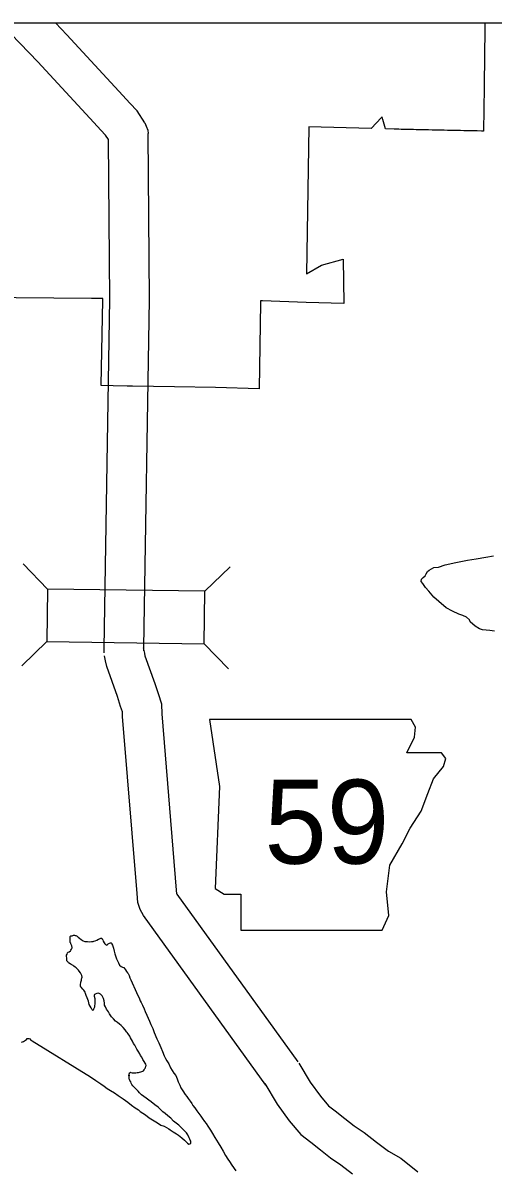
# Model space of a CAD drawing. Extents: x 1370567 to 1373900, y 377514 to 379648.
# Drawn here: x 1370913.9 to 1370949.4, y 379466.1 to 379552.5 of the extents above; entities that cross this region are included whole.
import ezdxf

# ---------------------------------------------------------------- set-up
doc = ezdxf.new("R2010")
doc.units = 0
doc.layers.add('Default', color=7, linetype='Continuous')
doc.layers.add('Survey Symbols', color=7, linetype='Continuous')

msp = doc.modelspace()

# ---------------------------------------------------------------- linework, layer by layer
at = {"layer": 'Default'}
for p, q in [((1370915.775, 379509.822), (1370913.934, 379511.715)), ((1370927.654, 379509.657), (1370929.546, 379511.498)), ((1370915.72, 379505.863), (1370913.827, 379504.022)), ((1370927.599, 379505.698), (1370929.439, 379503.805))]:
    msp.add_line(p, q, dxfattribs=at)
for points in [[(1370920.362, 379543.744), (1370920.151, 379544.066), (1370919.798, 379544.447), (1370919.256, 379545.024), (1370915.03, 379549.598), (1370913.026, 379551.692), (1370912.226, 379552.541)], [(1370923.119, 379545.008), (1370922.524, 379545.918), (1370921.992, 379546.493), (1370921.45, 379547.07), (1370917.216, 379551.653), (1370916.365, 379552.541)], [(1370948.789, 379552.541), (1370948.771, 379551.179), (1370948.767, 379550.923), (1370948.747, 379549.429), (1370948.746, 379549.328), (1370948.735, 379548.543), (1370948.728, 379548.044), (1370948.723, 379547.68), (1370948.701, 379546.03), (1370948.678, 379544.379), (1370948.529, 379544.382), (1370948.204, 379544.388), (1370947.954, 379544.393), (1370947.704, 379544.398), (1370947.454, 379544.403), (1370947.204, 379544.408), (1370946.954, 379544.413), (1370946.704, 379544.418), (1370946.454, 379544.423), (1370946.203, 379544.428), (1370945.953, 379544.433), (1370945.703, 379544.437), (1370945.453, 379544.442), (1370945.113, 379544.449), (1370944.807, 379544.456), (1370944.529, 379544.463), (1370944.513, 379544.463), (1370944.279, 379544.468), (1370944.24, 379544.469), (1370944.1, 379544.473), (1370944.054, 379544.474), (1370943.96, 379544.476), (1370943.823, 379544.479), (1370943.67, 379544.483), (1370943.596, 379544.484), (1370943.386, 379544.489), (1370943.369, 379544.489), (1370943.142, 379544.495), (1370943.111, 379544.495), (1370942.916, 379544.5), (1370942.839, 379544.502), (1370942.689, 379544.505), (1370942.564, 379544.508), (1370942.466, 379544.51), (1370942.285, 379544.515), (1370942.232, 379544.516), (1370941.987, 379544.521), (1370941.935, 379544.523), (1370941.289, 379544.538), (1370941.08, 379545.241), (1370941.02, 379545.444), (1370940.989, 379545.41), (1370940.205, 379544.563), (1370935.483, 379544.696), (1370935.33, 379533.601), (1370936.451, 379534.268), (1370938.091, 379534.722), (1370938.138, 379531.373), (1370935.3, 379531.432), (1370931.999, 379531.561), (1370931.848, 379531.567), (1370931.846, 379531.417), (1370931.751, 379524.935)], [(1370923.119, 379545.008), (1370923.217, 379544.758), (1370923.333, 379544.455), (1370923.364, 379544.199)], [(1370920.052, 379505.011), (1370920.034, 379505.357), (1370920.466, 379531.696), (1370920.367, 379543.747)], [(1370923.048, 379505.167), (1370923.035, 379505.41), (1370923.466, 379531.683), (1370923.364, 379544.199)], [(1370931.751, 379524.935), (1370928.449, 379525.024), (1370925.351, 379525.077), (1370922.177, 379525.131), (1370921.777, 379525.138), (1370920.733, 379525.156), (1370919.825, 379525.171), (1370919.825, 379525.186), (1370919.825, 379525.196), (1370919.932, 379531.621), (1370919.934, 379531.744), (1370919.306, 379531.75), (1370919.295, 379531.75), (1370919.098, 379531.752), (1370913.4, 379531.805), (1370908.872, 379531.864)], [(1370949.513, 379506.638), (1370949.154, 379506.686), (1370948.605, 379506.752), (1370948.385, 379506.831), (1370948.044, 379507.029), (1370947.673, 379507.347), (1370947.622, 379507.487), (1370947.392, 379507.696), (1370947.131, 379507.824), (1370946.812, 379507.922), (1370946.331, 379508.159), (1370945.851, 379508.396), (1370945.299, 379508.873), (1370944.938, 379509.221), (1370944.566, 379509.65), (1370944.304, 379509.938), (1370944.103, 379510.237), (1370943.982, 379510.387), (1370944.001, 379510.567), (1370944.12, 379510.698), (1370944.278, 379510.829), (1370944.357, 379510.97), (1370944.446, 379511.141), (1370944.575, 379511.242), (1370944.754, 379511.353), (1370944.923, 379511.454), (1370945.291, 379511.477), (1370945.789, 379511.66), (1370946.586, 379511.815), (1370947.462, 379512.011), (1370948.13, 379512.106), (1370948.847, 379512.221), (1370949.435, 379512.335)], [(1370934.677, 379474.148), (1370925.56, 379486.798), (1370925.541, 379486.832), (1370925.517, 379487.112), (1370924.431, 379500.414), (1370924.387, 379501.132), (1370924.134, 379501.903), (1370923.884, 379502.669), (1370923.144, 379504.755), (1370923.102, 379504.979), (1370923.021, 379505.383)], [(1370932.244, 379472.394), (1370923.016, 379485.196), (1370922.773, 379485.643), (1370922.588, 379486.166), (1370922.528, 379486.861), (1370921.439, 379500.199), (1370921.416, 379500.562), (1370921.283, 379500.97), (1370921.044, 379501.702), (1370920.238, 379503.971), (1370920.156, 379504.408), (1370920.079, 379504.795)], [(1370918.306, 379480.752), (1370918.256, 379480.862), (1370918.166, 379480.992), (1370918.106, 379481.052), (1370918.036, 379481.132), (1370917.925, 379481.251), (1370917.865, 379481.301), (1370917.765, 379481.361), (1370917.705, 379481.411), (1370917.555, 379481.48), (1370917.485, 379481.54), (1370917.355, 379481.63), (1370917.335, 379481.67), (1370917.235, 379481.769), (1370917.215, 379481.899), (1370917.224, 379481.99), (1370917.204, 379482.1), (1370917.213, 379482.2), (1370917.243, 379482.27), (1370917.283, 379482.37), (1370917.332, 379482.411), (1370917.392, 379482.451), (1370917.492, 379482.531), (1370917.531, 379482.581), (1370917.571, 379482.652), (1370917.621, 379482.742), (1370917.62, 379482.802), (1370917.61, 379482.862), (1370917.6, 379482.902), (1370917.59, 379482.952), (1370917.54, 379483.042), (1370917.519, 379483.102), (1370917.479, 379483.162), (1370917.469, 379483.262), (1370917.479, 379483.362), (1370917.468, 379483.442), (1370917.478, 379483.512), (1370917.478, 379483.562), (1370917.488, 379483.612), (1370917.537, 379483.643), (1370917.627, 379483.663), (1370917.737, 379483.694), (1370917.807, 379483.694), (1370917.866, 379483.684), (1370917.916, 379483.674), (1370917.956, 379483.654), (1370917.996, 379483.624), (1370918.076, 379483.555), (1370918.177, 379483.475), (1370918.307, 379483.385), (1370918.387, 379483.326), (1370918.447, 379483.276), (1370918.577, 379483.226), (1370918.686, 379483.216), (1370918.786, 379483.217), (1370918.966, 379483.208), (1370919.085, 379483.218), (1370919.205, 379483.238), (1370919.255, 379483.249), (1370919.355, 379483.289), (1370919.484, 379483.33), (1370919.624, 379483.4), (1370919.693, 379483.43), (1370919.793, 379483.491), (1370919.833, 379483.491), (1370919.883, 379483.441), (1370919.903, 379483.411), (1370919.933, 379483.341), (1370919.973, 379483.241), (1370920.034, 379483.131), (1370920.104, 379483.042), (1370920.144, 379482.992), (1370920.184, 379482.972), (1370920.224, 379482.962), (1370920.284, 379482.992), (1370920.343, 379483.042), (1370920.393, 379483.083), (1370920.453, 379483.113), (1370920.513, 379483.123), (1370920.563, 379483.123), (1370920.603, 379483.093), (1370920.623, 379483.074), (1370920.633, 379483.024), (1370920.663, 379482.944), (1370920.744, 379482.734), (1370920.804, 379482.504), (1370920.855, 379482.304), (1370920.926, 379482.073), (1370920.986, 379481.914), (1370921.046, 379481.764), (1370921.127, 379481.614), (1370921.207, 379481.454), (1370921.327, 379481.334), (1370921.427, 379481.294), (1370921.517, 379481.265), (1370921.587, 379481.195), (1370921.648, 379481.095), (1370921.738, 379480.975), (1370921.798, 379480.875), (1370921.848, 379480.815), (1370921.919, 379480.666)], [(1370921.922, 379473.007), (1370921.917, 379473.117), (1370921.926, 379473.197), (1370921.936, 379473.237), (1370921.956, 379473.277), (1370921.966, 379473.307), (1370921.986, 379473.327), (1370921.996, 379473.347), (1370922.026, 379473.357), (1370922.065, 379473.347), (1370922.165, 379473.328), (1370922.285, 379473.328), (1370922.425, 379473.329), (1370922.544, 379473.339), (1370922.624, 379473.35), (1370922.704, 379473.37), (1370922.804, 379473.39), (1370922.883, 379473.411), (1370922.953, 379473.431), (1370923.023, 379473.471), (1370923.073, 379473.541), (1370923.122, 379473.642), (1370923.152, 379473.702), (1370923.191, 379473.822), (1370923.211, 379473.872), (1370923.201, 379473.962), (1370923.14, 379474.052), (1370923.07, 379474.182), (1370922.97, 379474.332), (1370922.879, 379474.512), (1370922.789, 379474.632), (1370922.729, 379474.742), (1370922.618, 379474.951), (1370922.518, 379475.111), (1370922.428, 379475.261), (1370922.347, 379475.401), (1370922.267, 379475.541), (1370922.186, 379475.701), (1370922.116, 379475.841), (1370922.036, 379475.97), (1370921.975, 379476.09), (1370921.855, 379476.26), (1370921.775, 379476.36), (1370921.725, 379476.42), (1370921.624, 379476.57), (1370921.484, 379476.739), (1370921.334, 379476.889), (1370921.204, 379476.999), (1370921.054, 379477.118), (1370920.904, 379477.228), (1370920.753, 379477.397), (1370920.603, 379477.547), (1370920.453, 379477.767), (1370920.362, 379477.917), (1370920.232, 379478.116), (1370920.141, 379478.296), (1370920.081, 379478.426), (1370920.061, 379478.576), (1370920.04, 379478.746), (1370919.989, 379478.936), (1370919.889, 379479.136), (1370919.779, 379479.266), (1370919.679, 379479.306), (1370919.589, 379479.325), (1370919.499, 379479.295), (1370919.409, 379479.275), (1370919.38, 379479.264), (1370919.32, 379479.224), (1370919.29, 379479.174), (1370919.28, 379479.114), (1370919.331, 379478.924), (1370919.342, 379478.744), (1370919.332, 379478.503), (1370919.323, 379478.393), (1370919.303, 379478.273), (1370919.274, 379478.173), (1370919.244, 379478.113), (1370919.214, 379478.052), (1370919.185, 379478.022), (1370919.144, 379478.072), (1370919.064, 379478.232), (1370918.923, 379478.482), (1370918.853, 379478.722), (1370918.772, 379478.972), (1370918.691, 379479.162), (1370918.641, 379479.292), (1370918.601, 379479.402), (1370918.5, 379479.562), (1370918.43, 379479.621), (1370918.3, 379479.771), (1370918.26, 379479.821), (1370918.26, 379479.881), (1370918.269, 379479.961), (1370918.289, 379480.151), (1370918.308, 379480.222), (1370918.328, 379480.322), (1370918.338, 379480.402), (1370918.357, 379480.462), (1370918.377, 379480.542), (1370918.347, 379480.652), (1370918.306, 379480.752)], [(1370921.919, 379480.666), (1370921.989, 379480.486), (1370922.06, 379480.326), (1370922.482, 379479.376), (1370922.703, 379478.906), (1370922.764, 379478.746), (1370922.834, 379478.617), (1370922.935, 379478.417), (1370923.055, 379478.157), (1370923.146, 379477.947), (1370923.267, 379477.667), (1370923.357, 379477.447), (1370923.468, 379477.217), (1370923.569, 379476.957), (1370923.709, 379476.657), (1370923.83, 379476.368), (1370924.032, 379475.878), (1370924.182, 379475.578), (1370924.313, 379475.238), (1370924.444, 379474.918), (1370924.585, 379474.608), (1370924.686, 379474.398), (1370924.786, 379474.229), (1370924.917, 379474.009), (1370925.057, 379473.699), (1370925.188, 379473.489), (1370925.298, 379473.289), (1370925.467, 379473.123)], [(1370913.796, 379475.639), (1370913.945, 379475.68), (1370914.035, 379475.74), (1370914.104, 379475.781), (1370914.174, 379475.831), (1370914.244, 379475.901), (1370914.303, 379475.912), (1370914.363, 379475.902), (1370914.423, 379475.872), (1370914.513, 379475.792), (1370914.603, 379475.722), (1370919.015, 379473.027)], [(1370934.747, 379474.041), (1370935.606, 379472.607), (1370936.374, 379471.549), (1370936.97, 379470.84), (1370937.48, 379470.45), (1370938.219, 379469.87), (1370938.92, 379469.321), (1370939.664, 379468.803), (1370940.604, 379468.09), (1370941.497, 379467.409), (1370942.445, 379466.877), (1370943.728, 379465.851)], [(1370919.015, 379473.027), (1370919.417, 379472.751), (1370919.79, 379472.494), (1370920.041, 379472.307), (1370920.273, 379472.129), (1370920.534, 379471.972), (1370920.816, 379471.804), (1370921.107, 379471.617), (1370921.48, 379471.351), (1370921.832, 379471.094), (1370922.104, 379470.887), (1370922.396, 379470.68), (1370922.627, 379470.522), (1370922.758, 379470.393), (1370922.969, 379470.275), (1370923.161, 379470.137), (1370923.453, 379469.93), (1370923.684, 379469.772), (1370924.066, 379469.546), (1370924.327, 379469.378), (1370924.568, 379469.281), (1370924.93, 379469.084), (1370925.02, 379469.025), (1370925.262, 379468.877), (1370925.493, 379468.719), (1370925.664, 379468.611), (1370925.896, 379468.423), (1370926.118, 379468.225), (1370926.269, 379468.077), (1370926.339, 379468.018), (1370926.44, 379467.938), (1370926.52, 379467.949), (1370926.579, 379467.99), (1370926.599, 379468.04), (1370926.598, 379468.09), (1370926.588, 379468.17), (1370926.547, 379468.24), (1370926.516, 379468.3), (1370926.486, 379468.369), (1370926.465, 379468.409), (1370926.353, 379468.648), (1370926.252, 379468.787), (1370926.11, 379468.946), (1370925.918, 379469.134), (1370925.676, 379469.372), (1370925.475, 379469.52), (1370925.283, 379469.678), (1370925.081, 379469.886), (1370924.86, 379470.074), (1370924.648, 379470.242), (1370924.477, 379470.381), (1370924.285, 379470.549), (1370924.124, 379470.717), (1370923.872, 379470.915), (1370923.6, 379471.122), (1370923.419, 379471.26), (1370923.217, 379471.399), (1370923.036, 379471.527), (1370922.865, 379471.645), (1370922.724, 379471.814), (1370922.602, 379471.943), (1370922.471, 379472.092), (1370922.34, 379472.22), (1370922.219, 379472.349), (1370922.138, 379472.448), (1370922.087, 379472.548), (1370922.046, 379472.638), (1370921.985, 379472.747), (1370921.964, 379472.807), (1370921.943, 379472.867), (1370921.933, 379472.927), (1370921.922, 379473.007), (1370921.951, 379473.137)], [(1370925.467, 379473.123), (1370925.56, 379472.874), (1370925.632, 379472.644), (1370925.745, 379472.375), (1370925.827, 379472.186), (1370925.989, 379471.947), (1370926.151, 379471.689), (1370926.273, 379471.53), (1370926.394, 379471.371), (1370926.526, 379471.172), (1370926.658, 379471.003), (1370926.749, 379470.854), (1370926.891, 379470.675), (1370927.043, 379470.457), (1370927.195, 379470.258), (1370927.266, 379470.159), (1370927.347, 379470.05), (1370927.449, 379469.89), (1370927.631, 379469.642), (1370927.733, 379469.503), (1370927.864, 379469.304), (1370927.976, 379469.135), (1370928.068, 379468.986), (1370928.21, 379468.747), (1370928.393, 379468.449), (1370928.647, 379468.031), (1370928.84, 379467.713), (1370929.033, 379467.404), (1370929.216, 379467.076), (1370929.389, 379466.808), (1370929.511, 379466.619), (1370929.683, 379466.34), (1370929.978, 379465.913)], [(1370932.173, 379472.501), (1370933.1, 379470.952), (1370934.009, 379469.7), (1370934.885, 379468.659), (1370935.642, 379468.079), (1370936.369, 379467.508), (1370937.136, 379466.907), (1370937.899, 379466.376), (1370938.788, 379465.702)], [(1370926.864, 379470.71), (1370926.891, 379470.675), (1370927.043, 379470.457), (1370927.195, 379470.258), (1370927.266, 379470.159), (1370927.347, 379470.05), (1370927.449, 379469.89), (1370927.631, 379469.642), (1370927.733, 379469.503), (1370927.864, 379469.304), (1370927.976, 379469.135), (1370928.068, 379468.986), (1370928.21, 379468.747), (1370928.393, 379468.449), (1370928.647, 379468.031), (1370928.84, 379467.713), (1370929.033, 379467.404), (1370929.216, 379467.076), (1370929.389, 379466.808), (1370929.511, 379466.619), (1370929.683, 379466.34), (1370929.978, 379465.913)]]:
    msp.add_lwpolyline(points, dxfattribs=at)
for points in [[(1370915.72, 379505.863), (1370927.599, 379505.698), (1370927.654, 379509.657), (1370915.775, 379509.822)], [(1370927.994, 379499.99), (1370928.756, 379494.914), (1370928.417, 379487.217), (1370929.094, 379486.794), (1370930.363, 379486.794), (1370930.363, 379484.087), (1370941.021, 379484.087), (1370941.529, 379485.187), (1370941.359, 379486.963), (1370941.613, 379488.993), (1370942.544, 379490.6), (1370943.136, 379491.785), (1370943.982, 379493.053), (1370944.489, 379494.407), (1370944.912, 379495.507), (1370945.673, 379496.437), (1370945.843, 379497.029), (1370945.504, 379497.452), (1370942.882, 379497.452), (1370943.474, 379498.636), (1370943.559, 379499.398), (1370943.208, 379499.982)]]:
    msp.add_lwpolyline(points, close=True, dxfattribs=at)
at = {"layer": 'Survey Symbols'}
msp.add_lwpolyline([(1370727.274, 379552.541), (1371456.671, 379552.541), (1371456.671, 378768.055), (1370727.274, 378768.055)], close=True, dxfattribs=at)
msp.add_lwpolyline([(1370727.274, 379552.541), (1371456.671, 379552.541), (1371456.671, 378768.055), (1370727.274, 378768.055)], close=True, dxfattribs=at)
msp.add_lwpolyline([(1370727.274, 379552.541), (1371456.671, 379552.541), (1371456.671, 378768.055), (1370727.274, 378768.055)], close=True, dxfattribs=at)
msp.add_lwpolyline([(1370727.274, 379552.541), (1371456.671, 379552.541), (1371456.671, 378768.055), (1370727.274, 378768.055)], close=True, dxfattribs=at)
msp.add_lwpolyline([(1370727.274, 379552.541), (1371456.671, 379552.541), (1371456.671, 378768.055), (1370727.274, 378768.055)], close=True, dxfattribs=at)
msp.add_lwpolyline([(1370727.274, 379552.541), (1371456.671, 379552.541), (1371456.671, 378768.055), (1370727.274, 378768.055)], close=True, dxfattribs=at)

# ---------------------------------------------------------------- texts
at = {"layer": 'Default'}
msp.add_text('59', height=6.336, dxfattribs=at).set_placement((1370932.141, 379489.101))

doc.saveas('drawing.dxf')
